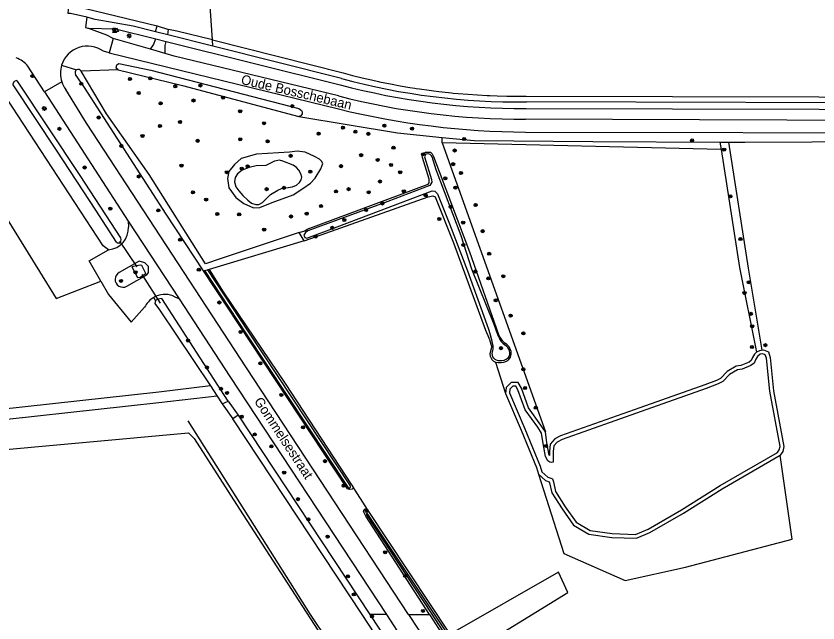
# Model space of a CAD drawing. Extents: x 137000 to 140001, y 403500 to 406000.
# Drawn here: x 138474.3 to 138682.6, y 405497.8 to 405655.3 of the extents above; entities that cross this region are included whole.
import ezdxf

# ---------------------------------------------------------------- set-up
doc = ezdxf.new("R2010")
doc.units = 0
for name, color, linetype in [('gg-afsc-draadraster', 7, 'Continuous'), ('gg-afsc-erfafscheiding', 7, 'Continuous'), ('gg-afsc-lijn draadraster', 7, 'Continuous'), ('gg-anno-openbare ruimte label', 7, 'Continuous'), ('gg-knt-bronhoudergrens', 7, 'Continuous'), ('gg-knt-onverhard', 7, 'Continuous'), ('gg-knt-verharding', 7, 'Continuous'), ('gg-knt-verharding nz', 7, 'Continuous'), ('gg-kntw-bovenkant insteek waterloop', 7, 'Continuous'), ('gg-kntw-midden sloot', 7, 'Continuous'), ('gg-kntw-waterlijn', 7, 'Continuous'), ('gg-kwrk-duiker nz buis', 7, 'Continuous'), ('gt-grn-groengrens', 7, 'Continuous'), ('gt-grn-groengrens NZ', 7, 'Continuous'), ('gt-grn-vlakafsluiter', 7, 'Continuous'), ('gt-grn-weggrens', 7, 'Continuous'), ('gt-symb-boom', 7, 'Continuous'), ('gt-symb-brandkraan', 7, 'Continuous'), ('gt-symb-lichtmast', 7, 'Continuous'), ('gt-symb-waterafsluiter', 7, 'Continuous')]:
    doc.layers.add(name, color=color, linetype=linetype)

# ---------------------------------------------------------------- blocks, each defined once
blk = doc.blocks.new('gt0-BOOM')
at = {"layer": 'gt-symb-boom'}
for radius in [0.4, 0.2]:
    blk.add_circle((0, 0), radius, dxfattribs=at)
blk = doc.blocks.new('gt0-WAFSL')
at = {"layer": 'gt-symb-waterafsluiter'}
for p, q in [((-0.5, -0.33), (0, 0.67)), ((0, 0.67), (0.5, -0.33)), ((0.5, -0.33), (-0.5, -0.33))]:
    blk.add_line(p, q, dxfattribs=at)
blk = doc.blocks.new('gt0-BR')
at = {"layer": 'gt-symb-brandkraan'}
for centre, radius, start, end in [((-0.24, 0), 0.206, 107.5669, 252.4331), ((0.6, -2.66), 3, 106.892, 107.5669), ((0, -0.69), 0.938, 73.108, 106.892), ((-0.6, -2.66), 3, 72.4331, 73.108), ((0.24, 0), 0.206, 287.567, 72.4331), ((0.6, 2.66), 3, 252.4331, 253.108), ((0, 0.69), 0.938, 253.108, 286.8921), ((-0.6, 2.66), 3, 286.8921, 287.567)]:
    blk.add_arc(centre, radius, start, end, dxfattribs=at)
blk = doc.blocks.new('gt0-LMAST')
at = {"layer": 'gt-symb-lichtmast'}
for p, q in [((-0.18, 0.17), (-0.45, 0.44)), ((-0.01, 0.25), (-0.01, 0.62)), ((0.17, 0.17), (0.44, 0.44)), ((-0.26, 0), (-0.63, 0)), ((-0.18, -0.18), (-0.45, -0.45)), ((-0.01, -0.25), (-0.01, -0.63)), ((0.44, -0.45), (0.17, -0.18)), ((0.24, 0), (0.62, 0))]:
    blk.add_line(p, q, dxfattribs=at)
blk.add_circle((-0.01, 0), 0.25, dxfattribs=at)

msp = doc.modelspace()

# ---------------------------------------------------------------- linework, layer by layer
at = {"layer": 'gg-afsc-draadraster'}
msp.add_lwpolyline([(138285.47, 405546.77), (138385.85, 405542.03), (138429.7, 405539.4), (138436.46, 405539.56), (138519.15, 405547.11), (138520.63, 405545.63), (138532.33, 405527.32), (138568.1, 405472.11), (138619.55, 405394.28), (138620.49, 405392.37), (138614.17, 405385.79)], dxfattribs=at)
at = {"layer": 'gg-afsc-erfafscheiding'}
for points in [[(138486.54, 405703.68), (138489.13, 405679.79), (138489.39, 405662.02), (138489.53, 405657.88), (138510.97, 405652.71)], [(138525.36, 405649.07), (138524.7, 405659.15), (138524.24, 405662.49)], [(138525.36, 405649.07), (138516.07, 405651.35), (138513.9, 405651.81)]]:
    msp.add_lwpolyline(points, dxfattribs=at)
at = {"layer": 'gg-afsc-lijn draadraster'}
msp.add_lwpolyline([(138285.47, 405546.77), (138385.85, 405542.03), (138429.7, 405539.4), (138436.46, 405539.56), (138519.15, 405547.11), (138520.63, 405545.63), (138532.33, 405527.32), (138568.1, 405472.11), (138619.55, 405394.28), (138620.49, 405392.37), (138614.17, 405385.79)], dxfattribs=at)
at = {"layer": 'gg-knt-bronhoudergrens'}
msp.add_line((138565.57, 405527.2), (138561.81, 405533.23), dxfattribs=at)
for points in [[(138659.36, 405622.56), (138663.63, 405622.55), (138698.36, 405622.75), (138731.28, 405623.33), (138760.93, 405624.73), (138807.2, 405630.57), (138848.69, 405634.92), (138870.43, 405637.95), (138880.17, 405639.47), (138901.12, 405644.91), (138929.96, 405653.95), (138949.6, 405660.12), (138957.13, 405662.06), (138962.26, 405662.86), (138977.74, 405662.68)], [(138584.96, 405623.79), (138593.28, 405622.96), (138624.08, 405622.68), (138657.1, 405622.57)]]:
    msp.add_lwpolyline(points, dxfattribs=at)
at = {"layer": 'gg-knt-onverhard'}
msp.add_line((138453.8, 405631.99), (138484.73, 405581.93), dxfattribs=at)
at = {"layer": 'gg-knt-verharding'}
for p, q in [((138510.58, 405651.17), (138510.97, 405652.71)), ((138510.97, 405652.71), (138513.9, 405651.81)), ((138513.74, 405650.37), (138510.58, 405651.17)), ((138513.74, 405650.37), (138513.9, 405651.81)), ((138525.47, 405647.43), (138513.74, 405650.37)), ((138499.53, 405649.42), (138498.54, 405645.75)), ((138509.27, 405646.65), (138499.53, 405649.42)), ((138510.65, 405649.36), (138513.29, 405648.7)), ((138513.29, 405648.7), (138558.5, 405637.42)), ((138498.54, 405645.75), (138497.02, 405646.12)), ((138558.89, 405639.04), (138525.47, 405647.43)), ((138498.54, 405645.75), (138558.1, 405631.15)), ((138481.74, 405635.62), (138477.43, 405642.23)), ((138486.23, 405638.16), (138481.74, 405635.62)), ((138481.74, 405635.62), (138503.44, 405602.07)), ((138503.44, 405602.07), (138503.55, 405600.52)), ((138484.73, 405581.93), (138496.33, 405586.49)), ((138515.09, 405582.64), (138516.68, 405581.88)), ((138516.68, 405581.88), (138529.89, 405561.75)), ((138529.89, 405561.75), (138570.51, 405500)), ((138570.51, 405500), (138647.23, 405383.38)), ((138576.29, 405500), (138705.1, 405304.24))]:
    msp.add_line(p, q, dxfattribs=at)
for points in [[(138492.74, 405654.93), (138488.49, 405655.96), (138487.85, 405655.94), (138488, 405656.95), (138487.89, 405657.57)], [(138510.58, 405651.17), (138504.74, 405652.63), (138494.92, 405654.39), (138492.74, 405654.93)], [(138493.01, 405652.14), (138500.19, 405651.97), (138510.65, 405649.36)], [(138499.53, 405649.42), (138497.89, 405650.33), (138493.01, 405652.14)], [(138509.27, 405646.65), (138510, 405647.78), (138510.65, 405649.36)], [(138513.05, 405645.57), (138513.08, 405647.63), (138513.29, 405648.7)], [(138876.03, 405649.02), (138855.75, 405646.31), (138837.13, 405644.49), (138829.28, 405643.99), (138806.56, 405643.19), (138799.78, 405642.75), (138787.55, 405640.82), (138767.44, 405636.82), (138756.97, 405635.08), (138738.33, 405633.38), (138720.82, 405632.69), (138606.85, 405632.97)], [(138606.79, 405631.24), (138720.86, 405630.99), (138738.44, 405631.71), (138756.93, 405633.38), (138766.88, 405635.02), (138787.84, 405639.17), (138799.96, 405641.1), (138808.28, 405641.59), (138829.37, 405642.26), (138837.25, 405642.82), (138855.9, 405644.69), (138876.13, 405647.31)], [(138558.07, 405634.52), (138515.43, 405644.89), (138513.05, 405645.57)], [(138874.22, 405643.73), (138772.25, 405631.7), (138744, 405628.98), (138731.23, 405628.29), (138719.7, 405628.09), (138606.68, 405628.5)], [(138498.37, 405594.64), (138496.98, 405595.61), (138465.96, 405642.9)], [(138606.6, 405625.15), (138719.6, 405624.93), (138730.03, 405625.11), (138745.36, 405625.88), (138771.74, 405628.49), (138874.58, 405640.63)], [(138576.29, 405500), (138534.21, 405563.95), (138492.61, 405627.44), (138487.26, 405636.21)], [(138503.07, 405585.16), (138508.27, 405588.14), (138508.73, 405588.75), (138508.73, 405590.27), (138507.74, 405591.2), (138506.31, 405591.64), (138501.14, 405588.7)], [(138496.33, 405586.49), (138498.36, 405582.99), (138504.24, 405575.81), (138507.72, 405579.68)]]:
    msp.add_lwpolyline(points, dxfattribs=at)
for centre, radius, start, end in [((138492.89, 405640.43), 7.03, 54.0682, 162.5699), ((138471.67, 405637.38), 7.53, 40.0811, 69.2719), ((138492.89, 405640.43), 7.03, 162.5759, 198.7882), ((138492.87, 405640.41), 7.01, 198.7244, 216.8434), ((138604.74, 405808.86), 175.9, 254.8921, 270.6888), ((138606.01, 405816.94), 185.7, 255.1763, 270.2409), ((138605.89, 405821.37), 192.87, 255.644, 270.2345), ((138607.88, 405834.52), 209.37, 256.2456, 269.6501), ((138497.88, 405600.29), 5.67, 274.953, 2.3352), ((138502.08, 405586.91), 2.02, 117.7231, 299.4774), ((138513.02, 405577.15), 5.87, 120.0629, 154.4437), ((138513.02, 405577.16), 5.87, 69.2601, 120.0421)]:
    msp.add_arc(centre, radius, start, end, dxfattribs=at)
at = {"layer": 'gg-knt-verharding nz'}
for p, q in [((138513.05, 405645.57), (138509.27, 405646.65)), ((138503.44, 405602.07), (138516.68, 405581.88))]:
    msp.add_line(p, q, dxfattribs=at)
at = {"layer": 'gg-kntw-bovenkant insteek waterloop'}
for p, q in [((138657.1, 405622.57), (138657.41, 405620.62)), ((138657.1, 405622.57), (138659.36, 405622.56)), ((138549.16, 405596.94), (138524.5, 405589.53)), ((138524.83, 405559.27), (138526.55, 405556.66)), ((138526.55, 405556.66), (138527.85, 405554.68)), ((138527.85, 405554.68), (138529.41, 405555.37)), ((138587.09, 405494.89), (138565.57, 405527.2))]:
    msp.add_line(p, q, dxfattribs=at)
for points in [[(138500.84, 405641.31), (138500.38, 405641.76), (138500.52, 405642.6), (138501.05, 405642.99), (138509.35, 405641.24), (138547.79, 405631.27), (138548.44, 405630.78), (138548.64, 405630.44), (138548.65, 405629.91), (138548.31, 405629.4), (138547.74, 405629.21)], [(138523.03, 405589.17), (138513.34, 405603.82), (138492.1, 405636.68), (138489.8, 405640.12)], [(138547.87, 405599.07), (138527.35, 405592.22), (138523.56, 405591), (138508.89, 405614.17), (138497.83, 405629.93), (138491.23, 405641)], [(138500.84, 405641.31), (138517.57, 405637.24), (138547.74, 405629.21)], [(138501.09, 405596.29), (138500.67, 405596.36), (138500.4, 405596.63), (138495.05, 405604.87), (138485.03, 405620.21), (138473.59, 405637.42), (138473.57, 405637.78), (138473.94, 405638.36), (138474.34, 405638.54)], [(138501.09, 405596.29), (138501.43, 405596.53), (138501.65, 405597.18), (138501.53, 405597.71), (138490.96, 405613.85), (138474.68, 405638.39), (138474.34, 405638.54)], [(138659.36, 405622.56), (138664.43, 405589.84), (138668.05, 405568.6)], [(138532.76, 405618.31), (138531.04, 405616.71), (138529.6, 405614.91), (138529.26, 405613.13), (138529.57, 405610.66), (138531.45, 405608.15), (138533.52, 405606.63), (138535.99, 405605.47), (138537.61, 405605.59), (138540.84, 405606.85), (138546.26, 405608.88), (138548.83, 405610.48), (138550.82, 405611.86), (138552.02, 405613.17), (138553.49, 405615.58), (138554.02, 405617.02), (138553.69, 405617.57), (138553.11, 405618.13), (138551.84, 405618.84), (138549.46, 405619.91), (138547.38, 405620.2), (138545.36, 405619.91), (138536.78, 405619.44), (138532.76, 405618.31)], [(138547.87, 405599.07), (138549.36, 405599.57), (138549.98, 405599.98), (138581.36, 405611.64), (138581.59, 405611.99), (138581.59, 405612.92), (138579.85, 405618.6), (138579.79, 405619.11), (138580.14, 405619.56), (138580.65, 405619.93), (138581.41, 405619.98), (138581.97, 405619.93), (138582.37, 405619.53), (138582.71, 405618.83), (138592.06, 405594.09), (138599.62, 405572.61)], [(138657.41, 405620.62), (138662.24, 405589.98), (138666.64, 405568.05)], [(138549.16, 405596.94), (138549.4, 405597.01), (138581.39, 405608.34), (138582.61, 405608.59), (138583.18, 405608.33), (138587.93, 405596.42), (138596.25, 405573.71), (138597.13, 405571.8)], [(138508.05, 405588.44), (138506.99, 405590.5), (138506.53, 405590.66), (138504.4, 405590.16), (138505.85, 405587.45), (138506.59, 405587.49), (138508.05, 405588.44)], [(138524.5, 405589.53), (138528.16, 405583.74), (138544.2, 405559.92), (138561.44, 405533.66), (138561.81, 405533.23)], [(138561.81, 405533.23), (138561.87, 405532.75), (138561.63, 405532.5), (138560.94, 405532.41), (138560.4, 405532.6), (138523.03, 405589.17)], [(138510.57, 405581.49), (138510.39, 405580.65), (138511.61, 405579), (138524.83, 405559.27)], [(138529.41, 405555.37), (138512.24, 405581.93), (138511.16, 405581.83), (138510.57, 405581.49)], [(138597.68, 405568.77), (138597.77, 405568.97), (138597.85, 405569.15)], [(138597.85, 405569.15), (138597.88, 405569.34), (138597.86, 405569.48)], [(138666.64, 405568.05), (138666.12, 405567.55), (138665.58, 405566.66), (138665.22, 405565.88), (138664.68, 405565.48), (138662.58, 405564.57), (138661.38, 405564.4), (138659, 405563.04), (138657.25, 405561.24), (138656.25, 405560.73), (138653.18, 405559.58), (138636.34, 405553.58), (138615.72, 405546.3), (138614.26, 405545.52), (138613.01, 405544.18), (138612.84, 405542.28), (138612.83, 405541.21), (138612.78, 405541.28), (138612.2, 405544.52), (138611.79, 405547.37)], [(138668.05, 405568.6), (138668.41, 405568.62), (138669.71, 405568.11), (138670.19, 405566.67), (138671.08, 405558.03), (138673.76, 405543.57), (138673.48, 405542.28), (138672.81, 405541.3)], [(138611.79, 405547.37), (138610.66, 405549.11), (138607.42, 405553.59), (138605.59, 405558.72), (138604.7, 405560.2), (138602.88, 405560.21), (138601.63, 405558.87), (138601.41, 405557.33)], [(138601.41, 405557.33), (138605.5, 405547.79), (138609.48, 405538.08), (138610.01, 405536.43)], [(138610.01, 405536.43), (138611.87, 405534.76), (138612.81, 405534.42), (138612.91, 405534.15), (138613.49, 405531.53), (138616.12, 405527.37), (138619.09, 405523.18), (138623.09, 405520.78), (138629.09, 405519.97), (138635.43, 405519.75), (138638.91, 405521.24), (138647.7, 405526.26), (138657.72, 405532.55), (138672.81, 405541.3)], [(138581.67, 405500), (138565.16, 405525.53), (138564.61, 405526.67), (138564.62, 405527.07), (138564.96, 405527.42), (138565.57, 405527.2)], [(138581.67, 405500), (138591.86, 405484.24), (138603.98, 405466.37), (138610.91, 405455.35), (138611.5, 405455.08), (138612.09, 405455.37), (138612.35, 405455.87), (138612.53, 405456.52)]]:
    msp.add_lwpolyline(points, dxfattribs=at)
for centre, radius, start, end in [((138490.5, 405640.58), 0.841, 121.4891, 213.3813), ((138490.5, 405640.58), 0.841, 29.5689, 121.5082), ((138585.94, 405566.98), 12.19, 11.8464, 23.2593), ((138605.07, 405575.03), 5.96, 203.8572, 231.7107), ((138599.83, 405567.61), 2.44, 151.5324, 189.2924), ((138599.75, 405567.57), 3.22, 12.3873, 59.6021), ((138599.71, 405567.62), 2.33, 190.1094, 248.703), ((138600.62, 405567.78), 2.32, 297.2476, 11.9673), ((138599.85, 405570.22), 4.87, 258.3157, 292.0695)]:
    msp.add_arc(centre, radius, start, end, dxfattribs=at)
at = {"layer": 'gg-kntw-midden sloot'}
for p, q in [((138518.96, 405550.19), (138550.75, 405500)), ((138550.75, 405500), (138625.68, 405386.95))]:
    msp.add_line(p, q, dxfattribs=at)
at = {"layer": 'gg-kntw-waterlijn'}
for p, q in [((138549.16, 405596.94), (138547.87, 405599.07)), ((138524.5, 405589.53), (138524.03, 405589.42)), ((138523.03, 405589.17), (138523.26, 405589.23))]:
    msp.add_line(p, q, dxfattribs=at)
for points in [[(138599.68, 405571.92), (138599.07, 405573.53), (138598.51, 405575.24), (138592.66, 405589.57), (138589.93, 405598.21), (138583.48, 405615.34), (138582.37, 405618.75), (138582.23, 405619), (138581.92, 405619.34), (138581.42, 405619.52), (138580.77, 405619.44), (138580.38, 405618.73), (138582.22, 405612.88), (138582.35, 405612.12), (138581.8, 405611.29), (138570.92, 405607.13), (138550.14, 405599.56), (138549.52, 405599.12), (138549.07, 405598.39), (138549.35, 405597.78), (138549.85, 405597.63), (138557.7, 405600.53), (138582.38, 405609.94), (138583.1, 405609.8), (138583.78, 405609.14), (138586.89, 405601.35), (138591.54, 405589.19), (138596.57, 405575.24), (138597.04, 405574.03), (138597.6, 405572.06)], [(138536.73, 405616.37), (138534.85, 405615.98), (138533.09, 405615.25), (138531.86, 405614.3), (138531.24, 405613.35), (138531.09, 405612.23), (138531.45, 405610.93), (138532.21, 405609.9), (138533.24, 405608.71), (138534.49, 405607.49), (138535.52, 405606.72), (138536.59, 405606.32), (138537.41, 405606.35), (138538.32, 405606.86), (138540.44, 405608.93), (138542.28, 405610.12), (138543.28, 405610.49), (138546.14, 405610.95), (138547.18, 405611.41), (138547.93, 405612.03), (138548.34, 405612.72), (138548.54, 405613.43), (138548.28, 405614.32), (138547.79, 405615.25), (138547.15, 405615.95), (138546.27, 405616.54), (138543.66, 405617.57), (138542.74, 405617.87), (138541.43, 405617.6), (138540.27, 405617.03), (138539.21, 405616.48), (138536.73, 405616.37)], [(138523.26, 405589.23), (138533.93, 405573.05), (138560.51, 405532.98)], [(138524.03, 405589.42), (138534.56, 405573.47), (138561.14, 405533.39)], [(138661.71, 405563.43), (138659.61, 405562.24), (138657.85, 405560.42), (138656.65, 405559.81), (138653.52, 405558.64), (138636.68, 405552.64), (138616.12, 405545.39), (138614.88, 405544.72), (138613.97, 405543.75), (138613.84, 405542.23), (138613.8, 405539.54), (138613.49, 405539.43), (138612.98, 405539.48), (138612.48, 405539.85), (138611.83, 405540.93), (138611.21, 405544.35), (138610.83, 405547.02), (138609.83, 405548.55), (138606.53, 405553.11), (138604.68, 405558.29), (138604.13, 405559.2), (138603.31, 405559.21), (138602.58, 405558.42), (138602.44, 405557.46), (138606.43, 405548.17), (138610.42, 405538.43), (138610.88, 405537), (138612.4, 405535.63), (138613.21, 405535.34), (138613.61, 405535.14), (138613.87, 405534.43), (138614.43, 405531.92), (138616.95, 405527.93), (138619.79, 405523.93), (138623.43, 405521.75), (138629.18, 405520.97), (138635.24, 405520.75), (138638.47, 405522.13), (138647.19, 405527.12), (138657.21, 405533.41), (138672.11, 405542.05), (138672.54, 405542.68), (138672.74, 405543.59), (138670.09, 405557.89), (138669.21, 405566.46), (138668.91, 405567.35), (138668.25, 405567.61), (138667.57, 405567.56), (138666.91, 405566.92), (138666.46, 405566.19), (138666.02, 405565.23), (138665.19, 405564.61), (138662.86, 405563.6), (138661.71, 405563.43)], [(138668.05, 405568.6), (138667.4, 405568.35), (138666.64, 405568.05)], [(138565.32, 405525.86), (138582.13, 405500.3), (138592.32, 405484.54), (138604.44, 405466.67), (138611.02, 405456.21)], [(138611.83, 405456.77), (138590.4, 405488.95), (138586.64, 405494.59), (138565.69, 405526.04)]]:
    msp.add_lwpolyline(points, dxfattribs=at)
for centre, radius, start, end in [((138587.43, 405568.2), 10.88, 7.7191, 20.7803), ((138604.62, 405574.2), 5.44, 204.7362, 232.0468), ((138595.17, 405569.28), 3.06, 336.9551, 7.11), ((138600.16, 405567.75), 2.42, 15.5988, 62.7722), ((138599.48, 405567.58), 1.57, 161.6167, 222.0114), ((138600.78, 405567.79), 1.83, 316.6671, 19.6175), ((138599.87, 405567.96), 2.11, 222.6069, 271.7068), ((138600.08, 405569.16), 3.31, 267.427, 307.6948), ((138560.83, 405533.18), 0.375, 211.5456, 35.6227), ((138565.5, 405525.96), 0.204, 23.4221, 208.7018)]:
    msp.add_arc(centre, radius, start, end, dxfattribs=at)
at = {"layer": 'gg-kwrk-duiker nz buis'}
for p, q in [((138501.23, 405596.84), (138505.68, 405590.15)), ((138507.02, 405588.24), (138511.77, 405580.73))]:
    msp.add_line(p, q, dxfattribs=at)
at = {"layer": 'gt-grn-groengrens'}
for p, q in [((138584.96, 405622.36), (138584.96, 405623.79)), ((138510.57, 405581.49), (138510.08, 405582.23)), ((138598.87, 405565.45), (138601.41, 405557.33)), ((138527.85, 405554.68), (138530.63, 405550.76)), ((138532.01, 405551.66), (138566.17, 405500)), ((138566.17, 405500), (138643.11, 405383.67))]:
    msp.add_line(p, q, dxfattribs=at)
for points in [[(138584.96, 405622.36), (138589.27, 405610.54), (138611.79, 405547.37)], [(138524.83, 405559.27), (138511.38, 405557.67), (138456.11, 405551.62), (138432.28, 405548.99), (138432.01, 405549.85), (138410.47, 405604.16)], [(138526.55, 405556.66), (138511.42, 405554.88), (138456.15, 405548.84), (138429.04, 405545.84)], [(138610.01, 405536.43), (138616.63, 405515.81), (138632.51, 405508.79), (138648.15, 405512.24), (138675.88, 405519.49), (138672.81, 405541.3)], [(138590.85, 405489.25), (138617.65, 405505.69), (138615.19, 405510.98), (138587.09, 405494.89)]]:
    msp.add_lwpolyline(points, dxfattribs=at)
at = {"layer": 'gt-grn-groengrens NZ'}
for p, q in [((138500.84, 405641.31), (138491.23, 405641)), ((138529.41, 405555.37), (138532.01, 405551.66)), ((138532.01, 405551.66), (138530.63, 405550.76))]:
    msp.add_line(p, q, dxfattribs=at)
for points in [[(138525.36, 405649.07), (138559.27, 405640.49), (138561.72, 405639.85), (138564.18, 405639.24), (138566.64, 405638.67), (138568.5, 405638.27), (138568.71, 405638.22), (138569.12, 405638.13), (138571.6, 405637.64), (138574.09, 405637.17), (138576.59, 405636.74), (138577.94, 405636.53), (138578.22, 405636.49), (138579.09, 405636.36), (138581.59, 405636), (138582.85, 405635.84), (138584.11, 405635.68), (138586.62, 405635.4), (138587.46, 405635.32), (138587.82, 405635.29), (138589.14, 405635.16), (138591.67, 405634.95), (138594.19, 405634.78), (138596.72, 405634.64), (138597.12, 405634.63), (138597.37, 405634.62), (138599.25, 405634.55), (138601.78, 405634.48), (138604.31, 405634.46), (138606.84, 405634.47), (138720.79, 405634.19)], [(138547.74, 405629.21), (138573.38, 405624.95), (138584.96, 405623.79)], [(138640.98, 405382.9), (138564.2, 405500), (138530.63, 405550.76)]]:
    msp.add_lwpolyline(points, dxfattribs=at)
at = {"layer": 'gt-grn-vlakafsluiter'}
msp.add_line((138657.41, 405620.62), (138584.96, 405622.36), dxfattribs=at)
msp.add_lwpolyline([(138523.26, 405589.23), (138523.62, 405589.31), (138524.03, 405589.42)], dxfattribs=at)
at = {"layer": 'gt-grn-weggrens'}
for p, q in [((138525.47, 405647.43), (138525.36, 405649.07)), ((138486.18, 405642.53), (138490.06, 405641.3)), ((138570.51, 405500), (138566.17, 405500)), ((138576.29, 405500), (138581.67, 405500))]:
    msp.add_line(p, q, dxfattribs=at)
for points in [[(138492.74, 405654.93), (138492.35, 405652.26), (138493.01, 405652.14)], [(138496.33, 405586.49), (138493.31, 405591.71), (138498.37, 405594.64)]]:
    msp.add_lwpolyline(points, dxfattribs=at)

# ---------------------------------------------------------------- block references
at = {"layer": 'gt-symb-boom'}
for p in [(138478.57, 405639.68), (138491.26, 405637.69), (138503.93, 405638.92), (138509.21, 405639.1), (138515.7, 405637.04), (138522.22, 405637.23), (138506.2, 405635.29), (138520.43, 405633.35), (138528.12, 405634.1), (138511.89, 405632.61), (138546.06, 405631.87), (138495.8, 405628.93), (138532.54, 405630.54), (138511.7, 405626.71), (138516.93, 405627.78), (138538.76, 405627.45), (138569.99, 405626.81), (138485.61, 405625.99), (138552.91, 405624.74), (138559.24, 405626.29), (138562.47, 405625.26), (138565.81, 405624.7), (138577.18, 405626.04), (138507.17, 405624.14), (138521.52, 405622.89), (138532.55, 405623.29), (138539.66, 405622.76), (138590.71, 405623.35), (138649.9, 405623.01), (138501.68, 405621.54), (138572.35, 405621.1), (138588.23, 405620.38), (138658.22, 405620.61), (138545.64, 405618.98), (138563.96, 405619.17), (138580.02, 405619.41), (138517.31, 405616.46), (138534.47, 405616.28), (138558.72, 405616.3), (138568.26, 405617.94), (138571.74, 405616.63), (138587.86, 405616.82), (138492.16, 405615.96), (138529.07, 405614.74), (138532.96, 405615.69), (138550.74, 405614.86), (138574.08, 405614.71), (138589.88, 405614.53), (138506.21, 405613.62), (138568.82, 405612.34), (138585.81, 405613.17), (138539.42, 405610.34), (138543.89, 405610.68), (138560.69, 405610.34), (138588.43, 405610.71), (138520.27, 405609.51), (138557.45, 405609.75), (138565.93, 405609.55), (138575.04, 405609.78), (138580.73, 405608.73), (138659.86, 405608.47), (138523.71, 405607.64), (138553.56, 405605.94), (138569.49, 405606.62), (138593.69, 405606.21), (138498.81, 405605.29), (138511.27, 405604.82), (138526.59, 405603.89), (138532.28, 405603.79), (138549.82, 405604), (138565.22, 405604.92), (138587.19, 405605.76), (138545.72, 405603.24), (138559.58, 405602.35), (138584.26, 405602.62), (138590.44, 405601.66), (138538.77, 405599.84), (138556.48, 405600.3), (138552.15, 405598.04), (138595.53, 405599.44), (138516.95, 405597.22), (138590.5, 405595.88), (138662.47, 405597.39), (138597.2, 405593.58), (138521.8, 405589.45), (138505.36, 405588.77), (138593.59, 405588.98), (138597.01, 405587.19), (138600.88, 405587.75), (138501.6, 405586.54), (138664.61, 405586.19), (138663.51, 405583.4), (138527.13, 405580.93), (138598.91, 405581.51), (138602.77, 405577.52), (138665.17, 405578), (138665.49, 405574.76), (138532.64, 405573.29), (138606.09, 405572.93), (138519.02, 405571.04), (138600.28, 405569.08), (138665.43, 405569.38), (138668.95, 405569.87), (138537.78, 405565.16), (138523.9, 405564.07), (138606.09, 405563.57), (138527.59, 405558.54), (138606.54, 405558.74), (138529.14, 405557.48), (138543.22, 405556.96), (138609.33, 405553.62), (138532.94, 405551.3), (138548.87, 405548.53), (138536.33, 405546.7), (138540.66, 405543.61), (138611.98, 405543.68), (138554.56, 405539.76), (138543.96, 405536.79), (138559.4, 405533.39), (138547.53, 405529.91), (138565.36, 405526.85), (138550.25, 405524.66), (138555.24, 405520.18), (138570.2, 405516.12), (138575.39, 405509.99), (138560.49, 405509.87), (138562.06, 405505.18), (138579.99, 405500.91), (138566.76, 405499.52)]:
    msp.add_blockref('gt0-BOOM', p, dxfattribs=at)
at = {"layer": 'gt-symb-brandkraan'}
msp.add_blockref('gt0-BR', (138499.77, 405651.82), dxfattribs=at)
at = {"layer": 'gt-symb-lichtmast'}
for p in [(138503.71, 405650.11), (138481.69, 405631.26)]:
    msp.add_blockref('gt0-LMAST', p, dxfattribs=at)
at = {"layer": 'gt-symb-waterafsluiter'}
for p in [(138500.42, 405651.56), (138499.94, 405651.33)]:
    msp.add_blockref('gt0-WAFSL', p, dxfattribs=at)

# ---------------------------------------------------------------- texts
at = {"layer": 'gg-anno-openbare ruimte label'}
for s, rotation, p in [('Oude Bosschebaan', 346.7, (138532.6, 405637.68)), ('Gommelsestraat', 303.4, (138536.06, 405555.33))]:
    msp.add_text(s, height=2.5, rotation=rotation, dxfattribs=at).set_placement(p)

doc.saveas('drawing.dxf')
